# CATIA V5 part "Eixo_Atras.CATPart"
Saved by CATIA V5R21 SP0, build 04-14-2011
Part number: Eixo_Atras
Bounding box of the stored display mesh (mm): x -2 to 2, y 0 to 16, z -2 to 2
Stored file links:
  D:\CATIA\CADs\CHASSI\Direita\Motor\Eixo_Atras.CATPart
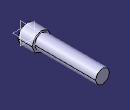
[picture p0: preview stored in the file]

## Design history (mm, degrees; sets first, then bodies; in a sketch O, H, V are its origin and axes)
Body1 (main body)
  Sketch1 on zx-plane, origin (0, 0, 0), H (-1, 0, 0), V (0, 0, 1)
    circle A1 centre (0, 0) radius 2
    radius A1 = 2
  Pad1: profile Sketch1, direction (0, 1, 0), length 3
  Sketch2 on end face of Pad1, origin (0, 3, 0), H (-1, 0, 0), V (0, 0, 1)
    circle A1 centre (0, 0.0956) radius 1.5
    point P1 (0, 0.0956)
    radius A1 = 1.5
    coincidence: P1 V
  Pad2: profile Sketch2, direction (0, 1, 0), length 13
